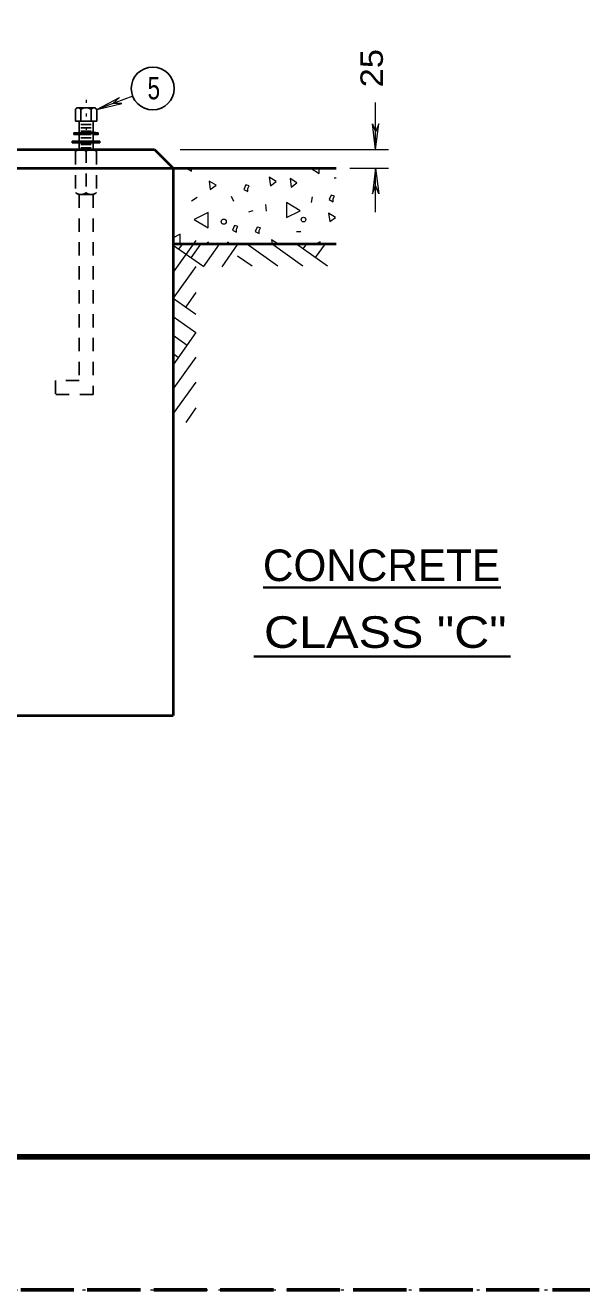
# Model space of a CAD drawing. Extents: x 312583 to 312854, y 144419 to 144597.
# Drawn here: x 312773.6 to 312792.43, y 144418.58 to 144461.41 of the extents above; entities that cross this region are included whole.
import ezdxf
from ezdxf.enums import TextEntityAlignment as Align

# ---------------------------------------------------------------- set-up
doc = ezdxf.new("R2010")
doc.units = 0
doc.header["$LTSCALE"] = 0.3
for name, pattern in [('DOTTED', [1.5, 0.3, -1.2]), ('LONG_DASHED', [7.5, 6, -1.5]), ('SHORT_DASHED', [2.7, 1.5, -1.2])]:
    doc.linetypes.add(name, pattern=pattern)
for name, color, linetype, lineweight in [('1', 7, 'Continuous', 25), ('2', 7, 'Continuous', 13), ('62', 7, 'DOTTED', 13), ('63', 7, 'LONG_DASHED', 60)]:
    doc.layers.add(name, color=color, linetype=linetype, lineweight=lineweight)

msp = doc.modelspace()

# ---------------------------------------------------------------- linework, layer by layer
at = {"layer": '1', "linetype": 'DOTTED', "lineweight": 13}
msp.add_line((312775.6593, 144458.8804), (312775.6593, 144457.2014), dxfattribs=at)
at = {"layer": '1'}
for p, q in [((312775.299, 144458.5507), (312775.299, 144458.1597)), ((312775.9276, 144458.612), (312775.391, 144458.612)), ((312775.483, 144458.5507), (312775.483, 144458.1597)), ((312775.8356, 144458.5507), (312775.8356, 144458.1597)), ((312776.0196, 144458.5507), (312776.0196, 144458.1597)), ((312776.0196, 144458.1597), (312775.299, 144458.1597)), ((312775.4216, 144458.1597), (312775.4216, 144457.2014)), ((312775.8356, 144458.0447), (312775.483, 144458.0447)), ((312775.8356, 144457.9374), (312775.483, 144457.9374)), ((312775.8356, 144457.8224), (312775.483, 144457.8224)), ((312775.897, 144458.1597), (312775.897, 144457.2014)), ((312776.127, 144457.485), (312775.1916, 144457.485)), ((312775.1916, 144457.485), (312775.1916, 144457.4237)), ((312776.127, 144457.4697), (312775.1916, 144457.4697)), ((312776.127, 144457.4544), (312775.1916, 144457.4544)), ((312776.127, 144457.439), (312775.1916, 144457.439)), ((312776.127, 144457.4237), (312775.1916, 144457.4237)), ((312775.2453, 144457.7687), (312775.2453, 144457.7074)), ((312775.6746, 144457.7687), (312775.2453, 144457.7687)), ((312775.6976, 144457.7074), (312775.2453, 144457.7074)), ((312775.8356, 144457.7074), (312775.483, 144457.7074)), ((312775.8356, 144457.5924), (312775.483, 144457.5924)), ((312775.8356, 144457.37), (312775.483, 144457.37)), ((312776.0733, 144457.7687), (312776.0733, 144457.7074)), ((312776.127, 144457.485), (312776.127, 144457.4237)), ((312775.8356, 144457.255), (312775.483, 144457.255))]:
    msp.add_line(p, q, dxfattribs=at)
at = {"layer": '1', "lineweight": 40}
for p, q in [((312734.5276, 144457.2014), (312777.9746, 144457.2014)), ((312777.9746, 144457.2014), (312778.611, 144456.565)), ((312771.3123, 144456.565), (312784.1233, 144456.565)), ((312778.611, 144456.565), (312778.611, 144438.0347)), ((312778.611, 144454.0044), (312784.1233, 144454.0044)), ((312733.8913, 144438.0347), (312778.611, 144438.0347))]:
    msp.add_line(p, q, dxfattribs=at)
at = {"layer": '1', "linetype": 'SHORT_DASHED'}
for p, q in [((312775.3066, 144457.14), (312775.3066, 144455.737)), ((312775.897, 144457.2014), (312775.4216, 144457.2014)), ((312775.8356, 144457.2014), (312775.483, 144457.2014)), ((312775.6593, 144457.2014), (312775.6593, 144455.6757)), ((312776.012, 144457.14), (312776.012, 144455.737)), ((312775.3066, 144456.2584), (312775.299, 144456.2507)), ((312775.4216, 144455.6757), (312775.4216, 144449.3737)), ((312775.8356, 144455.6757), (312775.483, 144455.6757)), ((312775.897, 144455.6757), (312775.897, 144448.8984)), ((312775.897, 144448.8984), (312774.6243, 144448.8984))]:
    msp.add_line(p, q, dxfattribs=at)
at = {"layer": '1', "lineweight": 158}
msp.add_line((312616.5, 144423.0846), (312849, 144423.0846), dxfattribs=at)
at = {"layer": '1'}
for points in [[(312775.414, 144458.612), (312775.6133, 144458.612), (312775.5826, 144458.6044), (312775.5596, 144458.5967), (312775.5213, 144458.5814), (312775.483, 144458.5584), (312775.4676, 144458.5814), (312775.4523, 144458.589), (312775.4216, 144458.6044), (312775.598, 144458.6044), (312775.5443, 144458.5967), (312775.5136, 144458.5814), (312775.483, 144458.566), (312775.4523, 144458.589), (312775.437, 144458.6044), (312775.575, 144458.6044), (312775.529, 144458.589), (312775.483, 144458.566), (312775.4446, 144458.6044), (312775.5596, 144458.6044), (312775.483, 144458.5737), (312775.4523, 144458.5967), (312775.5443, 144458.6044), (312775.483, 144458.5737), (312775.46, 144458.5967), (312775.529, 144458.5967), (312775.483, 144458.5814), (312775.4676, 144458.5967), (312775.5136, 144458.5967), (312775.483, 144458.5814), (312775.4753, 144458.5967), (312775.4983, 144458.589), (312775.483, 144458.589)], [(312775.9046, 144458.612), (312775.7053, 144458.612), (312775.736, 144458.6044), (312775.759, 144458.5967), (312775.7973, 144458.5814), (312775.8356, 144458.5584), (312775.851, 144458.5814), (312775.8663, 144458.589), (312775.897, 144458.6044), (312775.7206, 144458.6044), (312775.7743, 144458.5967), (312775.805, 144458.5814), (312775.8356, 144458.566), (312775.8663, 144458.589), (312775.8816, 144458.6044), (312775.7436, 144458.6044), (312775.7896, 144458.589), (312775.8356, 144458.566), (312775.874, 144458.6044), (312775.759, 144458.6044), (312775.8356, 144458.5737), (312775.8663, 144458.5967), (312775.7743, 144458.6044), (312775.8433, 144458.5737), (312775.8586, 144458.5967), (312775.7896, 144458.5967), (312775.8356, 144458.5814), (312775.851, 144458.5967), (312775.805, 144458.5967), (312775.8356, 144458.5814), (312775.8433, 144458.5967), (312775.8203, 144458.589), (312775.8356, 144458.589)], [(312776.0733, 144457.7687), (312775.6593, 144457.8224), (312775.6976, 144457.7074)], [(312775.897, 144457.7074), (312776.0733, 144457.715), (312776.0656, 144457.761), (312775.667, 144457.8147), (312775.6823, 144457.7687), (312775.9046, 144457.738), (312775.9046, 144457.715), (312776.0656, 144457.7227), (312776.058, 144457.7534), (312775.6823, 144457.807), (312775.69, 144457.7764), (312775.9123, 144457.738), (312775.9123, 144457.7227), (312776.058, 144457.7304), (312776.058, 144457.7457), (312775.6976, 144457.7994), (312775.6976, 144457.784), (312775.9123, 144457.7457), (312775.92, 144457.738), (312775.966, 144457.7304), (312776.0503, 144457.738), (312775.7053, 144457.7917), (312775.9966, 144457.738)], [(312775.6823, 144457.715), (312775.253, 144457.715), (312775.253, 144457.761), (312775.667, 144457.7534), (312775.6823, 144457.7227), (312775.2606, 144457.7227), (312775.2606, 144457.7534), (312775.667, 144457.7457), (312775.6746, 144457.7304), (312775.2683, 144457.7304), (312775.276, 144457.738), (312775.276, 144457.7457), (312775.6593, 144457.7457), (312775.667, 144457.738), (312775.276, 144457.738)], [(312775.6746, 144457.7687), (312776.0733, 144457.7074), (312775.897, 144457.7074)]]:
    msp.add_lwpolyline(points, dxfattribs=at)
at = {"layer": '1', "linetype": 'SHORT_DASHED'}
for points in [[(312775.7896, 144457.2014), (312775.529, 144457.2014), (312775.5596, 144457.1937), (312775.5826, 144457.186), (312775.6133, 144457.1707), (312775.6363, 144457.163), (312775.6593, 144457.1477), (312775.6593, 144457.14), (312775.7053, 144457.1707), (312775.7513, 144457.1937), (312775.7743, 144457.1937), (312775.5443, 144457.2014), (312775.5673, 144457.1937), (312775.5826, 144457.1937), (312775.6133, 144457.1784), (312775.644, 144457.163), (312775.6516, 144457.1554), (312775.6593, 144457.1477), (312775.7053, 144457.1784), (312775.7513, 144457.1937), (312775.5826, 144457.1937), (312775.621, 144457.1784), (312775.6593, 144457.1554), (312775.736, 144457.1937), (312775.598, 144457.1937), (312775.6593, 144457.1554), (312775.7206, 144457.186), (312775.6133, 144457.1937), (312775.6593, 144457.163), (312775.6976, 144457.186), (312775.6286, 144457.186), (312775.6593, 144457.1784), (312775.6976, 144457.1784), (312775.6746, 144457.1707), (312775.667, 144457.186), (312775.6593, 144457.163), (312775.644, 144457.1784), (312775.6363, 144457.1784), (312775.621, 144457.186)], [(312775.7896, 144455.6757), (312775.529, 144455.6757), (312775.5596, 144455.6834), (312775.5826, 144455.691), (312775.6133, 144455.6987), (312775.6363, 144455.714), (312775.6593, 144455.7294), (312775.6593, 144455.7294), (312775.7053, 144455.6987), (312775.7513, 144455.6834), (312775.7743, 144455.6757), (312775.5443, 144455.6757), (312775.5673, 144455.6834), (312775.5826, 144455.6834), (312775.6133, 144455.691), (312775.644, 144455.7064), (312775.6516, 144455.7217), (312775.6593, 144455.7294), (312775.7053, 144455.6987), (312775.7513, 144455.6834), (312775.5826, 144455.6834), (312775.621, 144455.691), (312775.6593, 144455.7217), (312775.736, 144455.6834), (312775.598, 144455.6834), (312775.6593, 144455.7217), (312775.7206, 144455.6834), (312775.6133, 144455.6834), (312775.6593, 144455.714), (312775.6976, 144455.691), (312775.6286, 144455.691), (312775.6593, 144455.6987), (312775.6976, 144455.691), (312775.6746, 144455.7064), (312775.667, 144455.691), (312775.6593, 144455.714), (312775.644, 144455.6987), (312775.6363, 144455.6987), (312775.621, 144455.691)], [(312775.4216, 144449.3737), (312774.6243, 144449.3737), (312774.6243, 144448.8984)]]:
    msp.add_lwpolyline(points, dxfattribs=at)
at = {"layer": '1'}
for centre, radius, start, end in [((312775.3906, 144458.5118), 0.0993, 25.60064, 154.39936), ((312775.6593, 144458.2985), 0.3126, 55.04559, 124.95441), ((312775.9279, 144458.5118), 0.0993, 25.60064, 154.39936)]:
    msp.add_arc(centre, radius, start, end, dxfattribs=at)
at = {"layer": '1', "linetype": 'SHORT_DASHED'}
for centre, start, end in [((312775.4845, 144456.9293), 50.00693, 129.99306), ((312775.8341, 144456.9293), 50.00694, 129.99307), ((312775.4845, 144455.9466), 230.00694, 309.99307), ((312775.8341, 144455.9466), 230.00693, 309.99306)]:
    msp.add_arc(centre, 0.272, start, end, dxfattribs=at)
at = {"layer": '2'}
for p, q in [((312777.2386, 144459.0107), (312776.0196, 144458.5507)), ((312776.0196, 144458.5507), (312776.794, 144458.957)), ((312776.0196, 144458.5507), (312776.8706, 144458.7577)), ((312776.794, 144458.957), (312776.5716, 144458.7577)), ((312776.8706, 144458.7577), (312776.5716, 144458.7577)), ((312785.4573, 144457.2014), (312785.4573, 144458.7884)), ((312785.35, 144458.0677), (312785.4573, 144457.7917)), ((312785.4573, 144457.2014), (312785.35, 144458.0677)), ((312785.5646, 144458.0677), (312785.4573, 144457.7917)), ((312785.4573, 144457.2014), (312785.5646, 144458.0677)), ((312778.841, 144457.2014), (312785.8943, 144457.2014)), ((312783.2646, 144456.565), (312783.5483, 144456.3887)), ((312783.5483, 144456.3887), (312783.5483, 144456.565)), ((312784.591, 144456.565), (312785.8943, 144456.565)), ((312785.4573, 144456.565), (312785.35, 144455.6987)), ((312785.4573, 144455.0777), (312785.4573, 144456.565)), ((312785.4573, 144456.565), (312785.5646, 144455.6987)), ((312778.611, 144456.3197), (312778.6493, 144456.312)), ((312784.0543, 144456.2354), (312784.1233, 144456.2354)), ((312785.35, 144455.6987), (312785.4573, 144455.9747)), ((312785.5646, 144455.6987), (312785.4573, 144455.9747)), ((312779.416, 144455.576), (312779.232, 144455.4457)), ((312780.566, 144455.622), (312780.6503, 144455.4534)), ((312781.7313, 144455.3307), (312781.7543, 144455.116)), ((312783.2953, 144455.4074), (312783.3183, 144455.5914)), ((312781.1716, 144455.093), (312781.3173, 144455.1314)), ((312782.7816, 144454.4184), (312782.9273, 144454.426)), ((312779.3776, 144454.1194), (312778.611, 144453.046)), ((312779.6076, 144453.2454), (312778.611, 144453.9507)), ((312778.91, 144453.9967), (312778.7873, 144453.828)), ((312779.5386, 144453.9967), (312779.2013, 144453.529)), ((312780.1673, 144453.9967), (312779.623, 144453.23)), ((312779.692, 144454.0044), (312779.8146, 144454.0734)), ((312780.7883, 144453.9967), (312780.2516, 144453.23)), ((312782.153, 144453.2454), (312781.0873, 144454.0044)), ((312782.9963, 144453.2454), (312781.9613, 144453.989)), ((312783.832, 144453.2454), (312782.7433, 144454.0197)), ((312783.119, 144454.0044), (312782.9963, 144453.8357)), ((312783.7476, 144454.0044), (312783.418, 144453.5444)), ((312781.279, 144453.2454), (312780.7883, 144453.5904)), ((312779.3776, 144453.2377), (312778.611, 144452.1644)), ((312779.3776, 144452.356), (312779.0326, 144451.873)), ((312778.611, 144452.1644), (312779.3776, 144451.6277)), ((312778.611, 144451.5434), (312779.3776, 144450.999)), ((312779.3776, 144450.999), (312778.6033, 144449.9104)), ((312778.611, 144450.9147), (312779.0786, 144450.5774)), ((312778.611, 144450.286), (312778.7796, 144450.1634)), ((312779.3776, 144450.1634), (312778.634, 144449.1284)), ((312779.3776, 144449.32), (312778.611, 144448.2544)), ((312779.3776, 144448.446), (312779.0326, 144447.9554))]:
    msp.add_line(p, q, dxfattribs=at)
at = {"layer": '2', "lineweight": 35}
for p, q in [((312781.6578, 144442.3663), (312789.7001, 144442.3663)), ((312781.3327, 144440.0295), (312790.0253, 144440.0295))]:
    msp.add_line(p, q, dxfattribs=at)
at = {"layer": '2'}
for points in [[(312779.1093, 144456.565), (312779.1016, 144456.5344), (312779.2243, 144456.4654), (312779.2243, 144456.565)], [(312778.841, 144454.0044), (312778.841, 144454.3264), (312778.611, 144454.2114)], [(312780.543, 144454.0044), (312780.451, 144454.058), (312780.4586, 144454.0044)], [(312782.1453, 144454.0044), (312781.9306, 144454.1347), (312781.9536, 144454.0044)], [(312783.579, 144454.0044), (312783.579, 144454.0734), (312783.4486, 144454.0044)]]:
    msp.add_lwpolyline(points, dxfattribs=at)
for points in [[(312779.8606, 144455.8444), (312780.06, 144455.99), (312779.8223, 144456.128)], [(312781.9, 144455.967), (312782.0916, 144456.1127), (312781.854, 144456.2584)], [(312782.6053, 144455.9287), (312782.797, 144456.0744), (312782.567, 144456.2124)], [(312781.1333, 144455.8827), (312781.1793, 144455.967), (312781.0643, 144455.9977), (312781.003, 144455.8444), (312781.1333, 144455.7754)], [(312784.0236, 144455.5377), (312784.0696, 144455.622), (312783.9546, 144455.6527), (312783.8933, 144455.507), (312784.0236, 144455.4304)], [(312782.4443, 144455.4074), (312782.4443, 144454.8937), (312782.912, 144455.1237)], [(312779.7916, 144454.541), (312779.7916, 144455.0624), (312779.324, 144454.8247)], [(312783.9086, 144454.7557), (312784.1003, 144454.9014), (312783.8703, 144455.0394)], [(312780.75, 144454.5104), (312780.796, 144454.5947), (312780.681, 144454.6254), (312780.6196, 144454.472), (312780.75, 144454.403)], [(312781.5166, 144454.4567), (312781.5626, 144454.541), (312781.4476, 144454.5717), (312781.3863, 144454.4184), (312781.5166, 144454.3494)]]:
    msp.add_lwpolyline(points, close=True, dxfattribs=at)
at = {"layer": '2', "lineweight": 25}
msp.add_circle((312777.9171, 144459.2663), 0.7254, dxfattribs=at)
at = {"layer": '2'}
for centre, radius in [((312780.3192, 144454.7548), 0.0865), ((312783.019, 144454.8253), 0.0784)]:
    msp.add_circle(centre, radius, dxfattribs=at)
at = {"layer": '62'}
msp.add_lwpolyline([(312601.2, 144418.5846), (312853.5, 144418.5846), (312853.5, 144596.7846)], dxfattribs=at)
at = {"layer": '63'}
msp.add_line((312851.75, 144418.5846), (312583.526, 144418.5846), dxfattribs=at)

# ---------------------------------------------------------------- texts
at = {"layer": '2', "width": 1.15}
msp.add_text('25 ', height=0.76, rotation=90, dxfattribs=at).set_placement((312785.7063, 144459.302))
at = {"layer": '2', "width": 0.75}
msp.add_text('5', height=0.76, dxfattribs=at).set_placement((312777.7415, 144458.8992))
at = {"layer": '2'}
msp.add_text('CONCRETE', height=1.07, dxfattribs=at).set_placement((312785.6604, 144442.5827), align=Align.CENTER)
at = {"layer": '2', "width": 1.15}
msp.add_text('CLASS "C"', height=1.07, dxfattribs=at).set_placement((312785.7863, 144440.321), align=Align.CENTER)

doc.saveas('drawing.dxf')
